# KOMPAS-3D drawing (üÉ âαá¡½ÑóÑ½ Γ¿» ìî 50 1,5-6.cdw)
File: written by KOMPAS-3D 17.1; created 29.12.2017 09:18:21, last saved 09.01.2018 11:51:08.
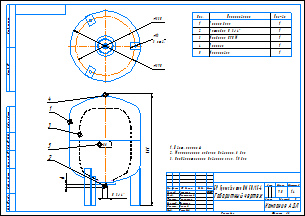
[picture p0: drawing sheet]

Sheet 1: A3, landscape, title-block layout from C:\Лощинин\GRAPHIC.LYT style 1

Title block, sheet 1: name: БР Гранлевел тип НМ 50/1,5-6 / Габаритный чертеж; mass: 9,8; sheets: 1; sheet format: A3; stored path: K:\АП\20_PKO\02_Насосное направление\Разработка\04_Проекты разные\Баки\КД действующая\Баки Flexcon R\Компас\Чертежи\БР Гранлевел тип НМ 50 1,5-6.cdw; drawn by: Лощинин; checked by: Хантимеров; drawn by, date: 29.12.2017

Views: Вид 1, Снизу
Referenced files in \\Fsk1\files\АП\20_PKO\02_Насосное направление\Разработка\04_Проекты разные\Баки\КД действующая\Баки Flexcon R\Компас\: 50 литров.a3d
Referenced files in C:\Лощинин\: GRAPHIC.LYT
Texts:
  IvAn
  ADL
  Цвет: красный
  Максимальное рабочее давление: 6 бар
  Предварительное давление газа: 1,5 бар
  ACAD_ISO03W100_RGB_223_127_255_SC_0.063_THICK_0.05
  ACAD_ISO03W100_RGB_223_127_255_SC_1_THICK_0.05
  Лит-Масса-Масштаб
  Материал-Предприятие
  Масштаб
  Изм.
  Лист
  № докум.
  Подп.
  Дата
  Лит.
  Разраб.
  Пров.
  Т.контр.
  Курлыкина
  Листов
  Нач.отд.
  Щетинин
  Н.контр.
  Долгов
  Утв.
  Рашидов
  Компания АДЛ
  Изменение
  Номер документа
  Подпись
  Обозначение документа
  Наименование изделия
  Масса изделия по ГОСТ 2.109-73
  Порядковый номер листа
  Общее количество листов в документе
  Характер работы, выполненной лицом, подписавшим документ
  Наименование или индекс предприятия, выпускающего документ
  Инв. № подл.
  Подп. и дата
  Взам. инв. №
  Инв. № дубл.
  Инвентарный номер подлинника по ГОСТ 2.501-68
  Подпись принявшего подлинник в отдел технической документации
  Инвентарный номер подлинника, взамен которого выпущен данный подлинник
  Инвентарный номер дубликата по ГОСТ 2.502-68
  Подпись принявшего дубликат в отдел технической документации
  Справ. №
  Перв. примен.
  Обозначение документа, взамен или на основании которого выпущен данный документ
  Обозначение документа, в котором впервые записан данный документ
  Подпись лица, копировавшего чертеж
  Обозначение формата листа
Dimensions and other numbers on the sheet: 330; 390; 13; 3 отв.; 1:4; 1; 9,8; 29.12.2017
